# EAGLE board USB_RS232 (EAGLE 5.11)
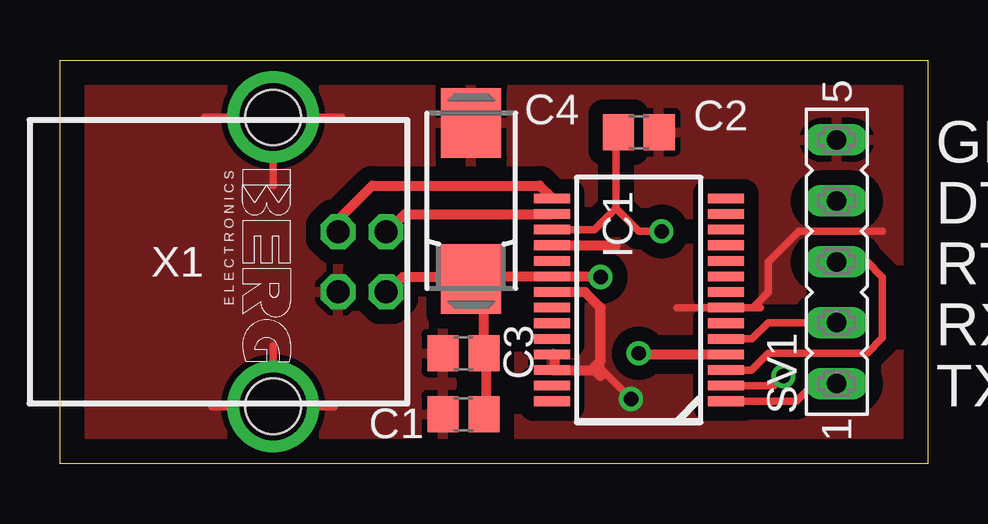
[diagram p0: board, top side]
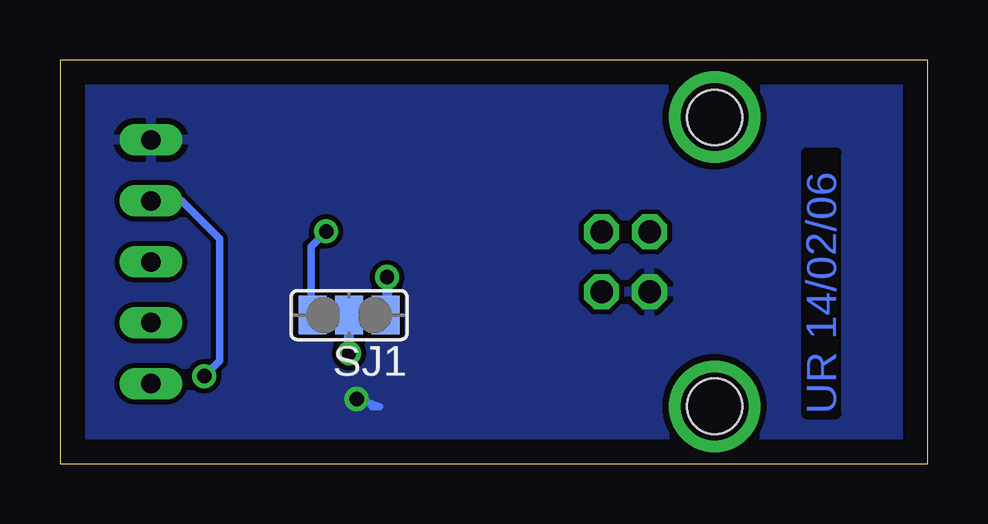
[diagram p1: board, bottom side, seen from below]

Size 36.17 x 16.82 mm. Coordinates in mm from the lower left corner, seen from the top.
Outline: 0,16.82 36.17,16.82 36.17,0 0,0 0,16.82
Copper layers (1*16): Top 0.035mm / dielectric 1.5mm / Bottom 0.035mm
Design rules "default": minimum track width 10mil, minimum drill 24mil, track to track 8mil, track to pad 8mil, pad to pad 8mil, via to via 8mil, smd to smd 8mil, copper to edge 40mil, drill to drill 8mil, minimum pad ring 10mil, minimum via ring 8mil, stop-mask expansion 4mil, vias tented up to drill 0mil, thermal gap 10mil

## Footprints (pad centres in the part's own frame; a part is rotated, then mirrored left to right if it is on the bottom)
C0805 = smd 1.3 x 1.5: 1 -0.85,0; 2 0.85,0
085CS_1AR = smd 2.9 x 2.5: + 3.25,0; - -3.25,0
SSOP28 = smd 0.4 x 1.5: 1 -4.225,-3.625; 2 -3.575,-3.625; 3 -2.925,-3.625; 4 -2.275,-3.625; 5 -1.625,-3.625; 6 -0.975,-3.625; 7 -0.325,-3.625; 8 0.325,-3.625; 9 0.975,-3.625; 10 1.625,-3.625; 11 2.275,-3.625; 12 2.925,-3.625; 13 3.575,-3.625; 14 4.225,-3.625; 15 4.225,3.625; 16 3.575,3.625; 17 2.925,3.625; 18 2.275,3.625; 19 1.625,3.625; 20 0.975,3.625; 21 0.325,3.625; 22 -0.325,3.625; 23 -0.975,3.625; 24 -1.625,3.625; 25 -2.275,3.625; 26 -2.925,3.625; 27 -3.575,3.625; 28 -4.225,3.625
SJ_2 = smd 1.168 x 1.6: 1 -1.524,0; 2 0,0; 3 1.524,0
FE05-1 = drill 0.813 long: 1 -5.08,0; 2 -2.54,0; 3 0,0; 4 2.54,0; 5 5.08,0
PN61729 = drill 0.95 octagon: 1 1.25,4.71; 2 -1.25,4.71; 3 -1.25,2.71; 4 1.25,2.71 | hole 2.3: -6.02,0; 6.02,0

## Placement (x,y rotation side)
C1  10nF  [C0805]  16.82,2.06 180 top
C2  100nF  [C0805]  24.12,13.81 0 top
C3  100nF  [C0805]  16.82,4.6 180 top
C4  22µ  [085CS_1AR]  17.14,10.95 270 top
IC1  FT232RL  [SSOP28]  24.12,6.82 90 top
SJ1  [SJ_2]  24.12,6.18 180 bottom
SV1  [FE05-1]  32.38,8.41 90 top
X1  [PN61729]  8.88,8.41 270 top

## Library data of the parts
C1-C4 = rcl
IC1 = FTDI
SJ1 = jumper
SV1 = con-lsta
X1 = con-berg

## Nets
DTR: IC1.2 SV1.4
GND: C1.2 C2.2 C3.2 C4.- IC1.7 IC1.18 IC1.21 IC1.25 IC1.26 SV1.5 X1.4
N$1: IC1.16 X1.2
N$2: IC1.15 X1.3
N$5: C2.1 IC1.17 SJ1.3
N$9: IC1.4 SJ1.2
RTS: IC1.3 SV1.3
RXD: IC1.5 SV1.2
TXD: IC1.1 SV1.1
VCC: C1.1 C3.1 C4.+ IC1.20 SJ1.1 X1.1

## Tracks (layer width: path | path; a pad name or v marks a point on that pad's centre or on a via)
DTR  (via drill 0.6)
  Top 0.305: IC1.2 29.76,3.25 v30.16,3.65
  Bottom 0.305: v30.16,3.65 29.52,4.28 29.52,9.36 31.11,10.95 SV1.4
GND  (via drill 0.6, 2.8 pad 3.81)
  Top 0.305: IC1.7 28.88,6.5 29.52,7.14 29.52,8.41 30.79,9.68 34.28,9.68 | 25.71,6.5 29.21,6.5 | v8.88,14.44 8.88,11.58 | 6.03,14.44 v8.88,14.44 | v8.88,14.44 11.74,14.44 | 6.34,2.38 v8.88,2.38 | v8.88,2.38 11.42,2.38 | v8.88,2.38 8.88,4.92 | 22.54,6.5 22.54,3.96 v23.81,2.69
  Top 0.406: 22.22,3.89 IC1.26 20.63,3.89 20.63,4.54 IC1.25 | 22.22,3.89 22.29,3.89 22.54,3.65 | IC1.21 21.89,7.14 22.54,6.5 22.54,4.28 22.22,3.96 22.22,3.89 | IC1.18 23.12,9.1 23.17,9.04
  Bottom 0.305: v23.81,2.69 22.86,2.38 23.17,2.38
  pour Top (isolate 0.61): -0.01,0.15 36.19,0.15 36.19,16.98 -0.01,16.98
  pour Bottom: -0.01,16.98 36.19,16.98 36.19,0.15 -0.01,0.15
N$1
  Top 0.406: X1.2 13.63,9.66 14.36,10.4 IC1.16
N$2
  Top 0.406: IC1.15 20.5,11.08 20,11.58 13.01,11.58 11.59,10.17 X1.3
N$5  (via drill 0.6)
  Top 0.305: IC1.17 22.29,9.75 23.17,10.63 | C2.1 23.17,13.81 23.17,10.63 | 23.17,10.63 24.12,9.68 v25.08,9.68
  Bottom 0.305: v25.08,9.68 25.71,9.04 25.71,6.18 SJ1.3
N$9  (via drill 0.6)
  Top 0.406: IC1.4 24.18,4.54 v24.12,4.6
  Bottom 0.406: v24.12,4.6 SJ1.2
RTS
  Top 0.305: IC1.3 28.82,3.89 29.52,4.6 33.65,4.6 34.28,5.23 34.28,7.77 33.65,8.41 SV1.3
RXD
  Top 0.305: IC1.5 28.85,5.2 29.52,5.87 SV1.2
TXD
  Top 0.305: IC1.1 30.7,2.59 31.43,3.33 SV1.1
VCC  (via drill 0.6)
  Top 0.406: C1.1 17.78,2.06 17.78,4.6 C3.1 17.67,7.24 17.14,7.77 | X1.1 13.67,7.16 14.28,7.77 17.14,7.77 | 17.14,7.77 C4.+ | 17.14,7.77 17.16,7.79 IC1.20 22.52,7.79 v22.54,7.77
  Bottom 0.406: SJ1.1 22.54,6.18 v22.54,7.77

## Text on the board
Bottom: UR 14/02/06
tPlace: GND | DTR | RTS | RXD | TXD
